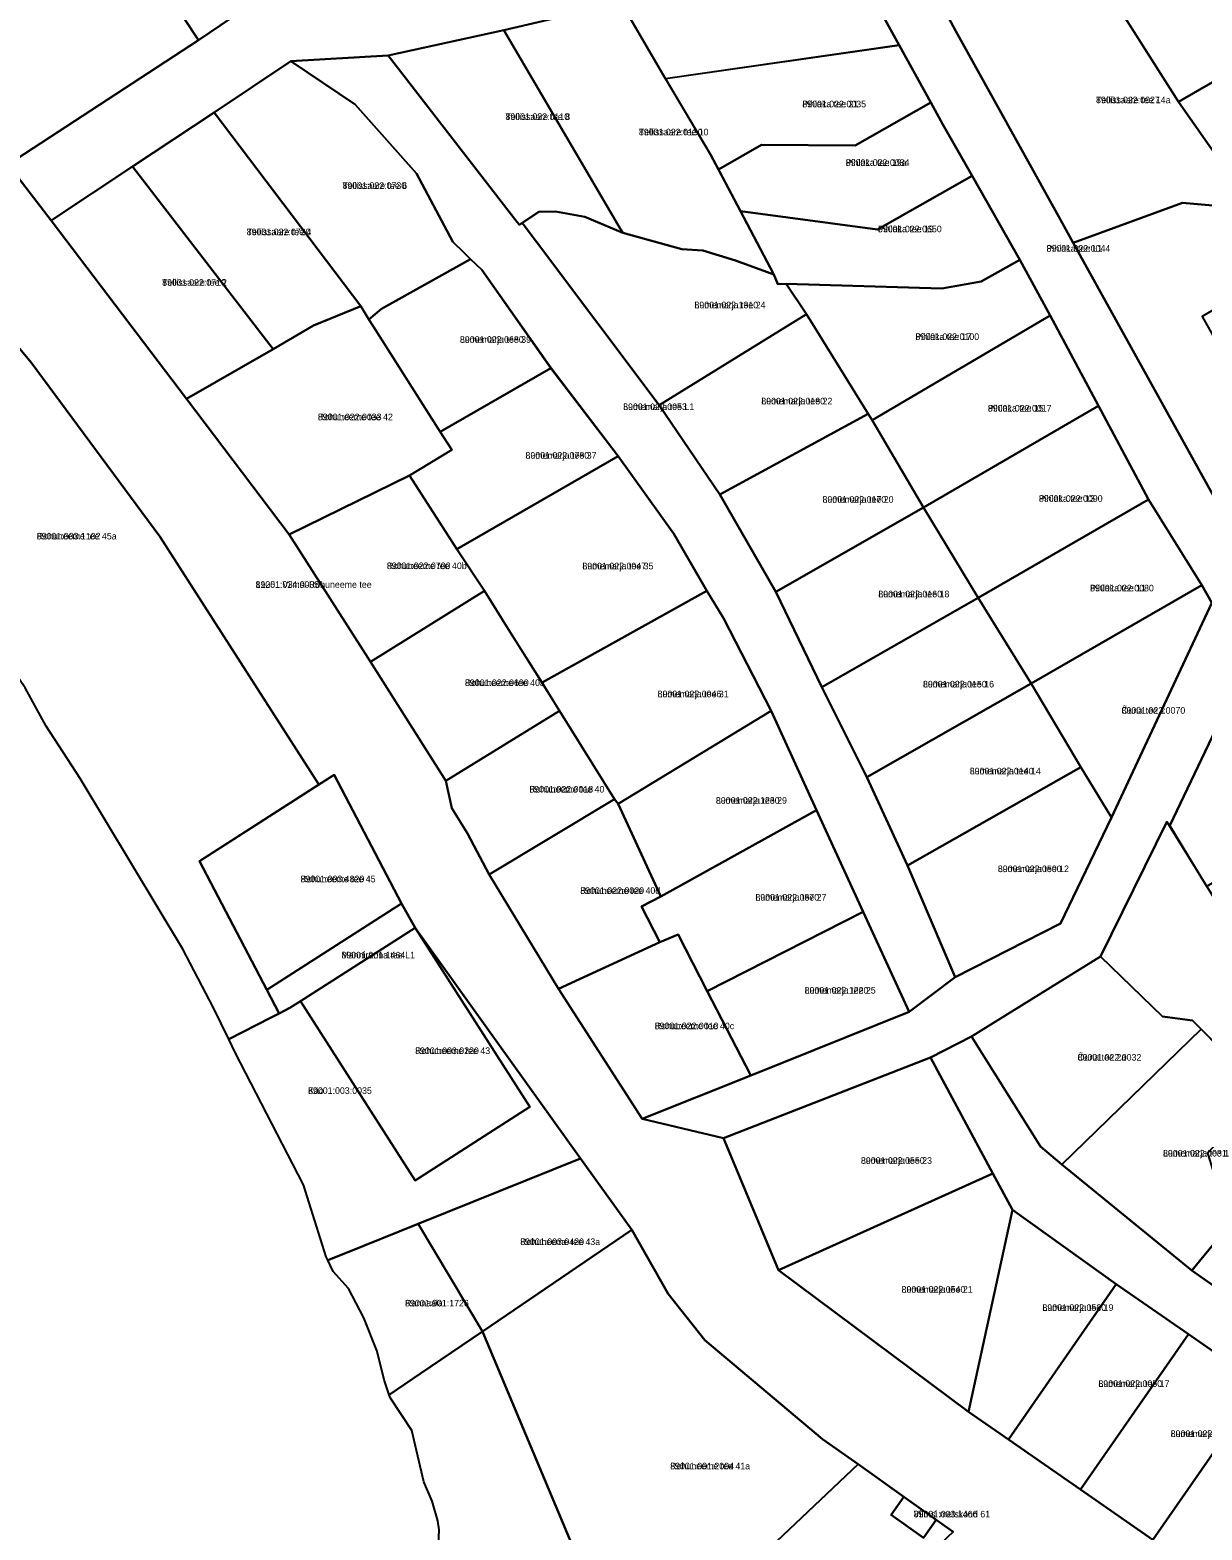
# Model space of a CAD drawing. Extents: x 526849 to 562296, y 6591741 to 6618546.
# Drawn here: x 545841.5 to 546108.1, y 6597929.8 to 6598270.9 of the extents above; entities that cross this region are included whole.
import ezdxf

# ---------------------------------------------------------------- set-up
doc = ezdxf.new("R2010")
doc.units = 0
for name, color, linetype in [('L_AADRESS', 7, 'Continuous'), ('PIIR', 7, 'Continuous'), ('TUNNUS', 7, 'Continuous')]:
    doc.layers.add(name, color=color, linetype=linetype)

msp = doc.modelspace()

# ---------------------------------------------------------------- linework, layer by layer
at = {"layer": 'PIIR'}
for points in [[(545893.04, 6598313.21), (545899.57, 6598281.95), (545879.86, 6598268.57), (545854.81, 6598306.43)], [(545852.64, 6598309.71), (545854.81, 6598306.43), (545879.86, 6598268.57), (545836.52, 6598240.3), (545804.14, 6598281.32)], [(546110.37, 6598140.63), (546108.1, 6598144.68), (546095.94, 6598164.16), (546084.55, 6598185.41), (546073.57, 6598205.99), (546066.7, 6598218.63), (546055.84, 6598237.71), (546049.19, 6598249.4), (546046.4, 6598254.43), (546039.19, 6598267.46), (546028.8, 6598286.32), (546042.81, 6598288.02), (546052.12, 6598270.62), (546075.45, 6598228.58), (546078.83, 6598222.48), (546116.7, 6598154.14)], [(546042.81, 6598288.02), (546081.89, 6598287.45), (546102.79, 6598254.56), (546112.94, 6598240.06), (546118.96, 6598234.99), (546125.21, 6598229.73), (546103.72, 6598231.57), (546078.83, 6598222.48), (546075.45, 6598228.58), (546052.12, 6598270.62)], [(546081.89, 6598287.45), (546083.01, 6598289.85), (546109.46, 6598287.9), (546120.25, 6598281.53), (546130.98, 6598270.84), (546102.79, 6598254.56)], [(545975.96, 6598277.04), (546028.8, 6598286.32), (546039.2, 6598267.43), (545986.09, 6598259.8)], [(545975.32, 6598226.54), (545949.3, 6598270.82), (545975.96, 6598277.04), (545986.09, 6598259.8), (545996.32, 6598242.61), (546003.14, 6598229.68), (546010.74, 6598215.26), (546001.98, 6598218.45), (545994.57, 6598220.73), (545989.77, 6598221.06), (545976.33, 6598224.75)], [(545949.3, 6598270.82), (545975.32, 6598226.54), (545976.33, 6598224.75), (545967.69, 6598228.44), (545961.04, 6598229.63), (545957.25, 6598229.53), (545952.82, 6598226.62), (545952.35, 6598227.18), (545922.97, 6598265.1)], [(546130.98, 6598270.84), (546153.28, 6598243.74), (546151.87, 6598232.37), (546151.42, 6598228.69), (546147.74, 6598227.79), (546125.21, 6598229.73), (546118.96, 6598234.99), (546112.94, 6598240.06), (546102.79, 6598254.56)], [(545986.08, 6598259.82), (546039.19, 6598267.46), (546046.4, 6598254.43), (546029.22, 6598244.63), (546007.9, 6598244.76), (545998.14, 6598239.15), (545996.32, 6598242.61)], [(545916.76, 6598208.12), (545883.4, 6598252.13), (545900.86, 6598263.76), (545915.44, 6598253.95), (545929.41, 6598238.26), (545937.66, 6598222.71), (545940.19, 6598220.28), (545941.74, 6598218.75), (545921.45, 6598207.45), (545918.6, 6598205.08)], [(546051.99, 6598055.51), (546041.48, 6598047.61), (546031.02, 6598070.39), (546020.41, 6598093.51), (546010.08, 6598116.05), (545999.29, 6598137.17), (545995.5, 6598143.39), (545987.97, 6598156.32), (545975.32, 6598174), (545960.03, 6598194.02), (545944.31, 6598216.34), (545941.74, 6598218.75), (545940.19, 6598220.28), (545937.66, 6598222.71), (545929.41, 6598238.26), (545915.44, 6598253.95), (545900.86, 6598263.76), (545922.97, 6598265.1), (545952.35, 6598227.18), (545952.82, 6598226.62), (545953.47, 6598227.04), (545956.73, 6598222.7), (545984.6, 6598185.59), (545998.4, 6598165.24), (546011.17, 6598143.16), (546021.61, 6598121.5), (546031.86, 6598100.99), (546041.15, 6598080.93)], [(545998.14, 6598239.15), (546007.9, 6598244.76), (546029.22, 6598244.63), (546046.4, 6598254.43), (546049.19, 6598249.4), (546055.84, 6598237.71), (546034.33, 6598225.55), (546003.14, 6598229.68)], [(545905.98, 6598203.73), (545896.78, 6598198.29), (545864.83, 6598239.86), (545883.4, 6598252.13), (545916.76, 6598208.12)], [(545864.83, 6598239.86), (545896.78, 6598198.29), (545877.1, 6598187.05), (545846.34, 6598227.57)], [(546034.32, 6598225.55), (546055.84, 6598237.71), (546066.7, 6598218.63), (546057.86, 6598213.68), (546048.9, 6598212.08), (546013.55, 6598213.2), (546011.66, 6598213.12), (546010.74, 6598215.26), (546003.14, 6598229.68)], [(545956.73, 6598222.7), (545953.47, 6598227.04), (545957.25, 6598229.53), (545961.04, 6598229.63), (545967.69, 6598228.44), (545976.33, 6598224.75), (545989.77, 6598221.06), (545994.57, 6598220.73), (546001.98, 6598218.45), (546010.74, 6598215.26), (546011.66, 6598213.12), (546013.55, 6598213.2), (546018.12, 6598206.28), (545984.6, 6598185.59)], [(546116.7, 6598154.14), (546078.83, 6598222.48), (546103.72, 6598231.57), (546125.21, 6598229.73), (546147.74, 6598227.79), (546151.42, 6598228.69), (546132.46, 6598188.03), (546118.9, 6598212.11), (546108.15, 6598205.72), (546125.97, 6598174.09)], [(545778.81, 6598197.53), (545791.98, 6598207.83), (545815.71, 6598226.51), (545841.77, 6598195.25), (545871.04, 6598155.73), (545907.22, 6598099.31), (545880.07, 6598081.89), (545895.37, 6598052.67), (545898.19, 6598047.28), (545896.17, 6598046.25), (545886.69, 6598041.4), (545883.27, 6598048.53), (545876.29, 6598061.87), (545852.9, 6598100.71), (545845.17, 6598112.56), (545840.41, 6598121.34), (545835.65, 6598128.22), (545827.39, 6598138.38), (545823.05, 6598142.51), (545819.77, 6598144.95), (545816.7, 6598148.54), (545809.51, 6598159.55), (545800.76, 6598170.68), (545788.97, 6598185.28)], [(545934.82, 6598179.55), (545919.55, 6598203.52), (545918.6, 6598205.08), (545921.45, 6598207.45), (545941.74, 6598218.75), (545944.28, 6598216.35), (545960, 6598194.02)], [(546032.17, 6598183.63), (546018.12, 6598206.28), (546013.55, 6598213.2), (546048.9, 6598212.08), (546057.86, 6598213.68), (546066.7, 6598218.63), (546073.57, 6598205.99), (546033.1, 6598182.17)], [(545877.1, 6598187.05), (545896.78, 6598198.29), (545905.98, 6598203.73), (545916.76, 6598208.12), (545918.6, 6598205.08), (545919.55, 6598203.52), (545934.82, 6598179.55), (545937.43, 6598175.46), (545927.85, 6598169.6), (545900.44, 6598156.19)], [(545984.6, 6598185.59), (546018.12, 6598206.28), (546032.17, 6598183.63), (545998.4, 6598165.24)], [(546033.1, 6598182.17), (546073.57, 6598205.99), (546084.55, 6598185.41), (546044.75, 6598162.28)], [(545927.85, 6598169.6), (545937.43, 6598175.46), (545934.82, 6598179.55), (545960, 6598194.02), (545975.32, 6598174), (545938.62, 6598152.83)], [(546044.75, 6598162.28), (546084.55, 6598185.41), (546095.94, 6598164.16), (546057.22, 6598141.81)], [(545998.4, 6598165.24), (546032.17, 6598183.63), (546033.1, 6598182.17), (546044.75, 6598162.28), (546011.17, 6598143.16)], [(545938.62, 6598152.83), (545975.32, 6598174), (545987.97, 6598156.32), (545995.5, 6598143.39), (545958, 6598122.5), (545950.32, 6598134.55), (545944.88, 6598143.35)], [(545918.94, 6598127.24), (545900.44, 6598156.19), (545927.85, 6598169.6), (545938.62, 6598152.83), (545944.88, 6598143.35)], [(546057.22, 6598141.81), (546095.94, 6598164.16), (546108.1, 6598144.68), (546069.25, 6598122.33)], [(546011.17, 6598143.16), (546044.75, 6598162.28), (546057.22, 6598141.81), (546021.61, 6598121.5)], [(546069.25, 6598122.33), (546108.1, 6598144.68), (546110.37, 6598140.63), (546087.53, 6598091.82), (546080.56, 6598103.31)], [(545918.94, 6598127.24), (545944.88, 6598143.35), (545950.32, 6598134.55), (545961.94, 6598116.12), (545936.11, 6598100.18)], [(545958, 6598122.5), (545995.5, 6598143.39), (545999.29, 6598137.17), (546010.08, 6598116.05), (545975.3, 6598094.95), (545974.48, 6598096.02), (545961.94, 6598116.12)], [(546021.61, 6598121.5), (546057.22, 6598141.81), (546069.25, 6598122.33), (546031.86, 6598100.99)], [(546139.88, 6598095.54), (546109.21, 6598076.15), (546100.78, 6598090), (546119.28, 6598128.76)], [(546080.56, 6598103.31), (546041.15, 6598080.93), (546031.86, 6598100.99), (546069.25, 6598122.33)], [(545936.11, 6598100.18), (545961.94, 6598116.12), (545974.48, 6598096.02), (545945.96, 6598078.9), (545941.02, 6598088.17), (545937.42, 6598093.97)], [(545975.3, 6598094.95), (546010.08, 6598116.05), (546020.41, 6598093.51), (545984.97, 6598073.87)], [(546075.96, 6598067.75), (546051.99, 6598055.51), (546041.15, 6598080.93), (546080.56, 6598103.31), (546087.53, 6598091.82)], [(545895.37, 6598052.67), (545880.07, 6598081.89), (545910.71, 6598101.55), (545926.01, 6598072.31)], [(545945.96, 6598078.9), (545974.48, 6598096.02), (545975.3, 6598094.95), (545984.97, 6598073.87), (545980.57, 6598071.56), (545984.77, 6598063.48), (545961.75, 6598052.9)], [(545984.97, 6598073.87), (546020.41, 6598093.51), (546031.02, 6598070.39), (545995.58, 6598052.36), (545988.91, 6598065.26), (545985.66, 6598063.88), (545984.77, 6598063.48), (545980.57, 6598071.56)], [(546100.13, 6598090.84), (546109.21, 6598076.15), (546123.97, 6598052.36), (546132.03, 6598039.02), (546122.27, 6598029.23), (546105.99, 6598045.66), (546099.1, 6598046.55), (546085.05, 6598060.2)], [(545895.37, 6598052.67), (545926.01, 6598072.31), (545929.11, 6598066.78), (545903.01, 6598050.05), (545900.62, 6598048.53), (545898.19, 6598047.28)], [(545995.58, 6598052.36), (546031.02, 6598070.39), (546041.48, 6598047.61), (546005.5, 6598033.18)], [(545908.88, 6597991.91), (545903.7, 6598008.31), (545888.14, 6598038.37), (545886.69, 6598041.4), (545896.17, 6598046.25), (545898.19, 6598047.28), (545900.62, 6598048.53), (545903.01, 6598050.05), (545929.1, 6598009.31), (545955.21, 6598026.03), (545929.11, 6598066.78), (545966.73, 6598014.3), (545929.82, 6597999.48), (545912.87, 6597992.65), (545909.23, 6597991.19)], [(545929.11, 6598066.78), (545955.21, 6598026.03), (545929.1, 6598009.31), (545903.01, 6598050.05)], [(545961.75, 6598052.9), (545984.77, 6598063.48), (545985.66, 6598063.88), (545988.91, 6598065.26), (545995.58, 6598052.36), (546005.5, 6598033.18), (545980.73, 6598023.3)], [(546055.65, 6598042.04), (546085.05, 6598060.2), (546099.1, 6598046.55), (546105.99, 6598045.66), (546107.91, 6598043.73), (546076.23, 6598012.92), (546071.36, 6598017.04)], [(546076.23, 6598012.92), (546107.91, 6598043.73), (546122.27, 6598029.23), (546109.4, 6598015.53), (546110.63, 6598011.44), (546118.77, 6598004.6), (546105.83, 6597988.84)], [(545999.28, 6598018.9), (546046.32, 6598037.28), (546060.56, 6598010.88), (546011.77, 6597988.9)], [(545966.73, 6598014.3), (545978.39, 6597998.07), (545944.41, 6597974.95), (545929.82, 6597999.48)], [(546060.56, 6598010.88), (546065.02, 6598002.6), (546055.02, 6597956.67), (546011.77, 6597988.9)], [(546137.78, 6597988.59), (546127.94, 6597973.3), (546105.83, 6597988.84), (546118.77, 6598004.6)], [(546055.02, 6597956.67), (546065.02, 6598002.6), (546088.6, 6597985.72), (546064.07, 6597950.41)], [(545944.41, 6597974.95), (545930.34, 6597965.43), (545923.22, 6597960.6), (545922.11, 6597963.76), (545920.42, 6597970.64), (545917.46, 6597978.05), (545913.96, 6597984.71), (545910.47, 6597988.63), (545909.23, 6597991.19), (545912.87, 6597992.65), (545929.82, 6597999.48)], [(545971.02, 6597911.58), (545944.41, 6597974.95), (545978.39, 6597998.07), (545986.7, 6597983.51), (545995.05, 6597972.99), (546021.8, 6597950.5), (546029.88, 6597944.77), (545981.4, 6597898.86)], [(546064.07, 6597950.41), (546088.6, 6597985.72), (546105.04, 6597974.33), (546080.51, 6597939.02)], [(546080.51, 6597939.02), (546105.04, 6597974.33), (546121.48, 6597962.95), (546096.95, 6597927.63)], [(546096.95, 6597927.63), (546121.48, 6597962.95), (546137.93, 6597951.56), (546113.4, 6597916.25)], [(545981.4, 6597898.86), (546029.88, 6597944.77), (546040.31, 6597937.34), (546037.4, 6597933.27), (546044.75, 6597928.04), (546047.65, 6597932.12), (546051.48, 6597929.4), (545997.86, 6597878.68)], [(546040.31, 6597937.34), (546047.65, 6597932.12), (546044.75, 6597928.04), (546037.4, 6597933.27)]]:
    msp.add_lwpolyline(points, close=True, dxfattribs=at)
for points in [[(545975.96, 6598277.04), (545949.3, 6598270.82), (545922.97, 6598265.1), (545900.86, 6598263.76), (545883.4, 6598252.13), (545864.83, 6598239.86), (545846.34, 6598227.57), (545836.52, 6598240.3), (545879.86, 6598268.57), (545899.57, 6598281.95)], [(545836.52, 6598240.3), (545846.34, 6598227.57), (545877.1, 6598187.05), (545900.44, 6598156.19), (545918.94, 6598127.24), (545936.11, 6598100.18), (545937.42, 6598093.97), (545941.02, 6598088.17), (545945.96, 6598078.9), (545961.75, 6598052.9), (545980.73, 6598023.3), (545999.28, 6598018.9), (546011.77, 6597988.9), (546055.02, 6597956.67), (546064.07, 6597950.41), (546080.51, 6597939.02), (546096.95, 6597927.63)], [(546051.48, 6597929.4), (546047.65, 6597932.12), (546040.31, 6597937.34), (546029.88, 6597944.77), (546021.8, 6597950.5), (545995.05, 6597972.99), (545986.7, 6597983.51), (545978.39, 6597998.07), (545966.73, 6598014.3), (545929.11, 6598066.78), (545926.01, 6598072.31), (545910.71, 6598101.55), (545907.22, 6598099.31), (545871.04, 6598155.73), (545841.77, 6598195.25), (545815.71, 6598226.51)], [(546119.28, 6598128.76), (546100.78, 6598090), (546100.13, 6598090.84), (546085.05, 6598060.2), (546055.65, 6598042.04), (546046.32, 6598037.28), (545999.28, 6598018.9), (545980.73, 6598023.3), (546005.5, 6598033.18), (546041.48, 6598047.61), (546051.99, 6598055.51), (546075.96, 6598067.75), (546087.53, 6598091.82), (546110.37, 6598140.63)], [(546170.81, 6597928.78), (546154.37, 6597940.18), (546137.93, 6597951.56), (546121.48, 6597962.95), (546105.04, 6597974.33), (546088.6, 6597985.72), (546065.02, 6598002.6), (546060.56, 6598010.88), (546046.32, 6598037.28), (546055.65, 6598042.04), (546071.36, 6598017.04), (546076.23, 6598012.92), (546105.83, 6597988.84), (546127.94, 6597973.3), (546138.76, 6597966.31), (546155.35, 6597954.77), (546171.72, 6597943.38), (546188.28, 6597932.07), (546205.13, 6597920.52)], [(545934.4, 6597926.41), (545934.6, 6597929.89), (545934.28, 6597931.9), (545933.01, 6597936.35), (545931.11, 6597940.79), (545928.36, 6597952.43), (545923.49, 6597959.84), (545923.22, 6597960.6), (545930.34, 6597965.43), (545944.41, 6597974.95), (545971.02, 6597911.58)]]:
    msp.add_lwpolyline(points, dxfattribs=at)

# ---------------------------------------------------------------- texts
at = {"layer": 'L_AADRESS'}
for s, p in [('Pihlaka tee 21', (546017.19, 6598253.3)), ('Tellissaare tee 14a', (546084.01, 6598254.24)), ('Tellissaare tee 8', (545949.65, 6598250.44)), ('Tellissaare tee 10', (545980.02, 6598246.93)), ('Pihlaka tee 19a', (546027.07, 6598239.99)), ('Tellissaare tee 6', (545912.57, 6598234.76)), ('Tellissaare tee 4', (545890.79, 6598224.23)), ('Pihlaka tee 19', (546034.4, 6598224.9)), ('Pihlaka tee L1', (546072.75, 6598220.47)), ('Tellissaare tee 2', (545871.56, 6598212.73)), ('Lumemarja tee 24', (545992.65, 6598207.61)), ('Pihlaka tee 17', (546042.92, 6598200.4)), ('Lumemarja tee 39', (545939.3, 6598199.76)), ('Lumemarja tee L1', (545976.43, 6598184.47)), ('Lumemarja tee 22', (546007.86, 6598185.76)), ('Pihlaka tee 15', (546059.4, 6598184.13)), ('Rohuneeme tee 42', (545906.98, 6598182.16)), ('Lumemarja tee 37', (545954.21, 6598173.42)), ('Lumemarja tee 20', (546021.78, 6598163.4)), ('Pihlaka tee 13', (546071.01, 6598163.61)), ('Rohuneeme tee 45a', (545843.02, 6598155.05)), ('Rohuneeme tee 40b', (545922.66, 6598148.31)), ('Lumemarja tee 35', (545967.16, 6598148.25)), ('11251 Viimsi-Rohuneeme tee', (545892.79, 6598144.05)), ('Pihlaka tee 11', (546082.66, 6598143.24)), ('Lumemarja tee 18', (546034.48, 6598141.89)), ('Rohuneeme tee 40a', (545940.44, 6598121.72)), ('Lumemarja tee 31', (545984.27, 6598119.17)), ('Lumemarja tee 16', (546044.64, 6598121.4)), ('Õuna tee 1', (546089.81, 6598115.43)), ('Lumemarja tee 14', (546055.29, 6598101.63)), ('Rohuneeme tee 40', (545955.11, 6598097.51)), ('Lumemarja tee 29', (545997.53, 6598094.96)), ('Lumemarja tee 12', (546061.68, 6598079.41)), ('Rohuneeme tee 45', (545903.04, 6598077.11)), ('Rohuneeme tee 40d', (545966.68, 6598074.46)), ('Lumemarja tee 27', (546006.52, 6598072.94)), ('Männiranna tee L1', (545912.35, 6598059.79)), ('Lumemarja tee 25', (546017.72, 6598051.79)), ('Rohuneeme tee 40c', (545983.62, 6598043.7)), ('Rohuneeme tee 43', (545929.11, 6598038.05)), ('Õuna tee 2a', (546079.82, 6598036.56)), ('Käo', (545904.75, 6598028.99)), ('Lumemarja tee 23', (546030.53, 6598013.09)), ('Lumemarja tee 12a', (546099.25, 6598014.75)), ('Rohuneeme tee 43a', (545953.02, 6597994.62)), ('Lumemarja tee 21', (546039.78, 6597983.78)), ('Rannaala', (545926.82, 6597980.66)), ('Lumemarja tee 19', (546071.81, 6597979.65)), ('Lumemarja tee 17', (546084.55, 6597962.37)), ('Lumemarja tee 15', (546100.99, 6597950.98)), ('Rohuneeme tee 41a', (545987.14, 6597943.62)), ('Viimsi metskond 61', (546042.53, 6597932.69))]:
    msp.add_text(s, height=1.5, dxfattribs=at).set_placement(p)
at = {"layer": 'TUNNUS'}
for s, p in [('89001:022:0035', (546017.19, 6598253.3)), ('89001:022:0027', (546084.01, 6598254.24)), ('89001:022:0110', (545949.65, 6598250.44)), ('89001:022:0130', (545980.02, 6598246.93)), ('89001:022:0034', (546027.07, 6598239.99)), ('89001:022:0730', (545912.57, 6598234.76)), ('89001:022:0720', (545890.79, 6598224.23)), ('89001:022:0650', (546034.4, 6598224.9)), ('89001:022:0044', (546072.75, 6598220.47)), ('89001:022:0710', (545871.56, 6598212.73)), ('89001:022:1310', (545992.65, 6598207.61)), ('89001:022:0100', (546042.92, 6598200.4)), ('89001:022:0680', (545939.3, 6598199.76)), ('89001:022:0053', (545976.43, 6598184.47)), ('89001:022:0180', (546007.86, 6598185.76)), ('89001:022:0017', (546059.4, 6598184.13)), ('89001:022:0033', (545906.98, 6598182.16)), ('89001:022:0780', (545954.21, 6598173.42)), ('89001:022:0170', (546021.78, 6598163.4)), ('89001:022:0090', (546071.01, 6598163.61)), ('89001:003:1102', (545843.02, 6598155.05)), ('89001:022:0700', (545922.66, 6598148.31)), ('89001:022:0047', (545967.16, 6598148.25)), ('89001:024:0005', (545892.79, 6598144.05)), ('89001:022:0080', (546082.66, 6598143.24)), ('89001:022:0160', (546034.48, 6598141.89)), ('89001:022:0690', (545940.44, 6598121.72)), ('89001:022:0046', (545984.27, 6598119.17)), ('89001:022:0150', (546044.64, 6598121.4)), ('89001:022:0070', (546089.81, 6598115.43)), ('89001:022:0140', (546055.29, 6598101.63)), ('89001:022:0018', (545955.11, 6598097.51)), ('89001:022:1230', (545997.53, 6598094.96)), ('89001:022:0500', (546061.68, 6598079.41)), ('89001:003:4820', (545903.04, 6598077.11)), ('89001:022:0020', (545966.68, 6598074.46)), ('89001:022:0870', (546006.52, 6598072.94)), ('89001:001:1464', (545912.35, 6598059.79)), ('89001:022:1220', (546017.72, 6598051.79)), ('89001:022:0010', (545983.62, 6598043.7)), ('89001:003:0220', (545929.11, 6598038.05)), ('89001:022:0032', (546079.82, 6598036.56)), ('89001:003:0035', (545904.75, 6598028.99)), ('89001:022:0550', (546030.53, 6598013.09)), ('89001:022:0031', (546099.25, 6598014.75)), ('89001:003:0420', (545953.02, 6597994.62)), ('89001:022:0540', (546039.78, 6597983.78)), ('89001:001:1726', (545926.82, 6597980.66)), ('89001:022:0530', (546071.81, 6597979.65)), ('89001:022:0050', (546084.55, 6597962.37)), ('89001:022:0520', (546100.99, 6597950.98)), ('89001:001:2004', (545987.14, 6597943.62)), ('89001:003:1466', (546042.53, 6597932.69))]:
    msp.add_text(s, height=1.5, dxfattribs=at).set_placement(p)

doc.saveas('drawing.dxf')
